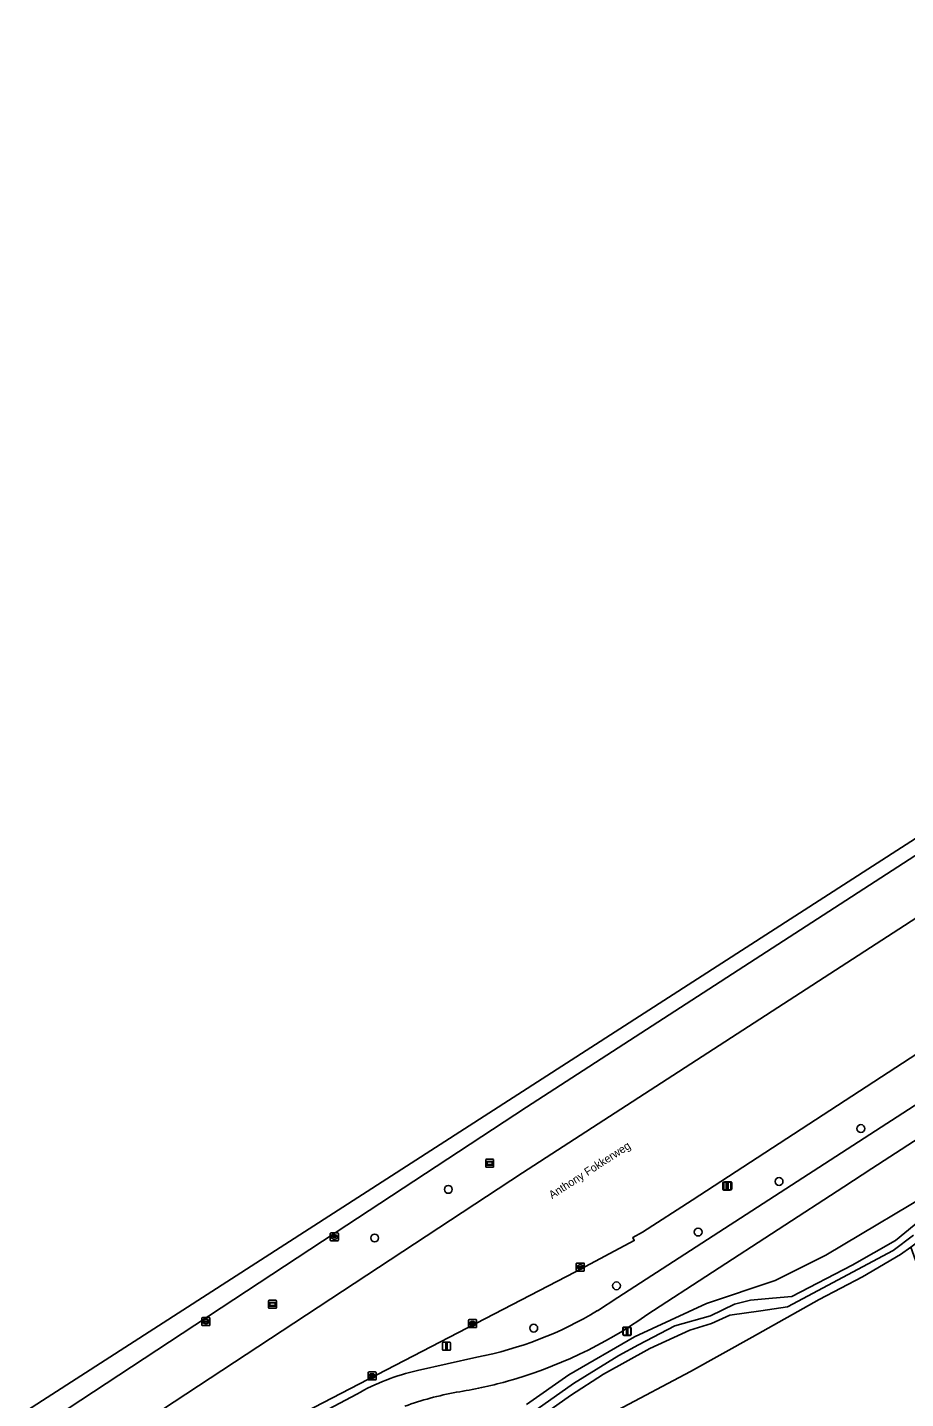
# Model space of a CAD drawing. Extents: x 156061 to 157804, y 383437 to 385640.
# Drawn here: x 156083.9 to 156193.6, y 385371.7 to 385543 of the extents above; entities that cross this region are included whole.
import ezdxf

# ---------------------------------------------------------------- set-up
doc = ezdxf.new("R2010")
doc.units = 0
for name, color, linetype in [('IMGEO_Berm_groen', 7, 'Continuous'), ('IMGEO_Boom', 7, 'Continuous'), ('IMGEO_Fietspad_gesloten', 7, 'Continuous'), ('IMGEO_Groenvoorziening', 7, 'Continuous'), ('IMGEO_Informatiebord', 7, 'Continuous'), ('IMGEO_Kolk', 7, 'Continuous'), ('IMGEO_Lichtmast', 7, 'Continuous'), ('IMGEO_Loofbos', 7, 'Continuous'), ('IMGEO_Oever', 7, 'Continuous'), ('IMGEO_Openbare_ruimte_label', 7, 'Continuous'), ('IMGEO_Rijbaan_regionaal_gesloten', 7, 'Continuous'), ('IMGEO_Waterloop', 7, 'Continuous')]:
    doc.layers.add(name, color=color, linetype=linetype)

msp = doc.modelspace()

# ---------------------------------------------------------------- linework, layer by layer
at = {"layer": 'IMGEO_Berm_groen'}
for points in [[(156360.66, 385543), (156360.46, 385542.87), (156346.09, 385533.56), (156314.1, 385512.84), (156302.47, 385505.41), (156290.49, 385497.87), (156278.52, 385490.5), (156266.95, 385483.55), (156254.78, 385476.36), (156243.16, 385469.51), (156215.23, 385452.76), (156213.93, 385451.91), (156195.47, 385439.96), (156146.25, 385408.11), (156122.36, 385392.42), (156089.02, 385370.47), (156093.27, 385365.39), (156145.76, 385399.91), (156224.68, 385450.98), (156281.69, 385487.99)], [(156362.88, 385518.97), (156357.59, 385515.73), (156355.55, 385514.47), (156333.02, 385500.08), (156304.54, 385485.41), (156304.35, 385485.8), (156253.2, 385452.66), (156166.98, 385396.48), (156160.76, 385392.48), (156159.54, 385391.82), (156159.73, 385391.43), (156152.38, 385387.55), (156100.57, 385360.69), (156097.06, 385358.97), (156097.83, 385357.84), (156097.99, 385357.93), (156125.07, 385372.26)], [(156155.15, 385382.68), (156157.66, 385384.33), (156254.84, 385447.18)], [(156132.64, 385375.2), (156140.06, 385376.88)]]:
    msp.add_lwpolyline(points, dxfattribs=at)
for centre, radius, start, end in [((156131.61, 385421.34), 45.26, 280.765, 301.337), ((156138.57, 385348.64), 27.21, 102.5918, 119.7557)]:
    msp.add_arc(centre, radius, start, end, dxfattribs=at)
at = {"layer": 'IMGEO_Boom'}
for centre in [(156188.04, 385405.43), (156136.5, 385397.83), (156177.82, 385398.82), (156167.71, 385392.5), (156127.3, 385391.76), (156157.51, 385385.79), (156147.17, 385380.5)]:
    msp.add_circle(centre, 0.489, dxfattribs=at)
at = {"layer": 'IMGEO_Fietspad_gesloten'}
for points in [[(156370.19, 385520.48), (156366.79, 385519.18), (156365.93, 385518.78), (156364.24, 385517.92), (156361.44, 385516.31), (156358.41, 385514.31), (156356.83, 385513.33), (156339.62, 385502.15), (156254.84, 385447.18), (156157.66, 385384.33), (156155.15, 385382.68)], [(156161.3, 385382.16), (156185.89, 385398.17), (156189.39, 385400.45), (156267.35, 385450.95)], [(156140.06, 385376.88), (156132.64, 385375.2)], [(156137.5, 385372.48), (156137.53, 385372.49)], [(156125.07, 385372.26), (156097.99, 385357.93), (156097.83, 385357.84), (156095.41, 385356.51), (156096.05, 385355.75), (156098.02, 385353.55), (156101.47, 385355.41), (156101.87, 385355.65), (156108.99, 385359.74), (156113.43, 385362.1)]]:
    msp.add_lwpolyline(points, dxfattribs=at)
for centre, radius, start, end in [((156131.61, 385421.34), 45.26, 280.765, 301.337), ((156128.8, 385428.03), 56.22, 285.4141, 305.3159), ((156138.57, 385348.64), 27.21, 102.5918, 119.7557), ((156144.4, 385334.13), 38.97, 100.1966, 109.9934), ((156128.82, 385427.97), 56.16, 278.9285, 285.4196)]:
    msp.add_arc(centre, radius, start, end, dxfattribs=at)
at = {"layer": 'IMGEO_Groenvoorziening'}
for points in [[(156376.46, 385518.83), (156375.61, 385518.52), (156373.73, 385517.99), (156368.95, 385515.98), (156366.21, 385514.72), (156363.43, 385513.21), (156271.3, 385453.51), (156267.35, 385450.95), (156189.39, 385400.45), (156185.89, 385398.17), (156161.3, 385382.16)], [(156146.27, 385370.97), (156151.56, 385374.68), (156159.75, 385379.43), (156168.75, 385383.56), (156177.32, 385386.43), (156183.65, 385389.61), (156198.62, 385398.53)], [(156137.53, 385372.49), (156137.5, 385372.48)]]:
    msp.add_lwpolyline(points, dxfattribs=at)
for centre, radius, start, end in [((156128.8, 385428.03), 56.22, 285.4141, 305.3159), ((156144.4, 385334.13), 38.97, 100.1966, 109.9934), ((156128.82, 385427.97), 56.16, 278.9285, 285.4196)]:
    msp.add_arc(centre, radius, start, end, dxfattribs=at)
at = {"layer": 'IMGEO_Informatiebord'}
for p, q in [((156141.27, 385401.59), (156142.06, 385401.59)), ((156142.06, 385401.59), (156141.27, 385401.59)), ((156141.17, 385400.69), (156141.17, 385401.49)), ((156141.17, 385401.49), (156141.17, 385400.69)), ((156142.06, 385400.59), (156141.27, 385400.59)), ((156141.27, 385400.59), (156142.06, 385400.59)), ((156142.16, 385401.49), (156142.16, 385400.69)), ((156142.16, 385400.69), (156142.16, 385401.49)), ((156114.04, 385383.08), (156114.04, 385383.88)), ((156114.04, 385383.88), (156114.04, 385383.08)), ((156114.14, 385383.98), (156114.93, 385383.98)), ((156114.93, 385383.98), (156114.14, 385383.98)), ((156114.93, 385382.98), (156114.14, 385382.98)), ((156114.14, 385382.98), (156114.93, 385382.98)), ((156115.03, 385383.88), (156115.03, 385383.08)), ((156115.03, 385383.08), (156115.03, 385383.88))]:
    msp.add_line(p, q, dxfattribs=at)
for points in [[(156141.27, 385401.33), (156142.06, 385401.33), (156142.06, 385400.86), (156141.27, 385400.86), (156141.27, 385401.33)], [(156141.34, 385401.26), (156141.34, 385400.93), (156141.99, 385400.93), (156141.99, 385401.26), (156141.34, 385401.26)], [(156114.15, 385383.72), (156114.93, 385383.72), (156114.93, 385383.25), (156114.15, 385383.25), (156114.15, 385383.72)], [(156114.21, 385383.65), (156114.21, 385383.32), (156114.87, 385383.32), (156114.87, 385383.65), (156114.21, 385383.65)]]:
    msp.add_lwpolyline(points, dxfattribs=at)
for centre, start, end in [((156141.27, 385401.49), 90, 180), ((156141.27, 385401.49), 90, 180), ((156142.06, 385401.49), 0, 90), ((156142.06, 385401.49), 360, 90), ((156141.27, 385400.69), 180, 270), ((156141.27, 385400.69), 180, 270), ((156142.06, 385400.69), 270, 0), ((156142.06, 385400.69), 270, 0), ((156114.14, 385383.88), 90, 180), ((156114.14, 385383.88), 90, 180), ((156114.14, 385383.08), 180, 270), ((156114.14, 385383.08), 180, 270), ((156114.93, 385383.88), 0, 90), ((156114.93, 385383.88), 360, 90), ((156114.93, 385383.08), 270, 0), ((156114.93, 385383.08), 270, 0)]:
    msp.add_arc(centre, 0.1, start, end, dxfattribs=at)
at = {"layer": 'IMGEO_Kolk'}
for p, q in [((156121.76, 385391.47), (156121.76, 385392.32)), ((156121.84, 385392.39), (156122.69, 385392.39)), ((156122.69, 385391.39), (156121.84, 385391.39)), ((156122.02, 385391.89), (156122.02, 385391.9)), ((156122.46, 385391.85), (156122.06, 385391.85)), ((156122.07, 385391.94), (156122.46, 385391.94)), ((156122.25, 385392.17), (156122.28, 385392.17)), ((156122.27, 385391.61), (156122.25, 385391.61)), ((156122.51, 385391.9), (156122.51, 385391.89)), ((156122.77, 385392.32), (156122.77, 385391.47)), ((156152.49, 385387.7), (156152.49, 385388.56)), ((156152.57, 385388.63), (156153.42, 385388.63)), ((156152.75, 385388.12), (156152.75, 385388.14)), ((156153.19, 385388.09), (156152.79, 385388.09)), ((156152.8, 385388.17), (156153.19, 385388.17)), ((156152.98, 385388.41), (156153.01, 385388.41)), ((156153, 385387.85), (156152.98, 385387.85)), ((156153.24, 385388.14), (156153.24, 385388.12)), ((156153.49, 385388.56), (156153.49, 385387.7)), ((156153.42, 385387.63), (156152.57, 385387.63)), ((156105.72, 385380.9), (156105.72, 385381.75)), ((156105.8, 385381.83), (156106.65, 385381.83)), ((156105.98, 385381.32), (156105.98, 385381.33)), ((156106.02, 385381.37), (156106.42, 385381.37)), ((156106.42, 385381.28), (156106.02, 385381.28)), ((156106.21, 385381.61), (156106.23, 385381.61)), ((156106.23, 385381.05), (156106.21, 385381.05)), ((156106.46, 385381.33), (156106.46, 385381.32)), ((156106.72, 385381.75), (156106.72, 385380.9)), ((156139.03, 385380.64), (156139.03, 385381.49)), ((156139.1, 385381.56), (156139.95, 385381.56)), ((156139.28, 385381.06), (156139.28, 385381.07)), ((156139.72, 385381.02), (156139.32, 385381.02)), ((156139.33, 385381.11), (156139.72, 385381.11)), ((156139.51, 385381.34), (156139.54, 385381.34)), ((156139.77, 385381.07), (156139.77, 385381.06)), ((156140.03, 385381.49), (156140.03, 385380.64)), ((156106.65, 385380.83), (156105.8, 385380.83)), ((156139.95, 385380.56), (156139.1, 385380.56)), ((156139.54, 385380.78), (156139.51, 385380.78)), ((156126.48, 385374.11), (156126.48, 385374.96)), ((156126.55, 385375.03), (156127.4, 385375.03)), ((156126.73, 385374.53), (156126.73, 385374.54)), ((156127.17, 385374.49), (156126.77, 385374.49)), ((156126.78, 385374.58), (156127.18, 385374.58)), ((156126.96, 385374.81), (156126.99, 385374.81)), ((156126.99, 385374.25), (156126.96, 385374.25)), ((156127.22, 385374.54), (156127.22, 385374.53)), ((156127.48, 385374.96), (156127.48, 385374.11)), ((156127.4, 385374.03), (156126.55, 385374.03))]:
    msp.add_line(p, q, dxfattribs=at)
for points in [[(156121.76, 385391.47), (156121.76, 385392.32)], [(156121.84, 385392.39), (156122.69, 385392.39)], [(156122.69, 385391.39), (156121.84, 385391.39)], [(156122.77, 385392.32), (156122.77, 385391.47)], [(156152.49, 385387.7), (156152.49, 385388.56)], [(156152.57, 385388.63), (156153.42, 385388.63)], [(156153.49, 385388.56), (156153.49, 385387.7)], [(156153.42, 385387.63), (156152.57, 385387.63)], [(156105.72, 385380.9), (156105.72, 385381.75)], [(156105.8, 385381.83), (156106.65, 385381.83)], [(156106.72, 385381.75), (156106.72, 385380.9)], [(156139.03, 385380.64), (156139.03, 385381.49)], [(156139.1, 385381.56), (156139.95, 385381.56)], [(156140.03, 385381.49), (156140.03, 385380.64)], [(156106.65, 385380.83), (156105.8, 385380.83)], [(156139.95, 385380.56), (156139.1, 385380.56)], [(156126.48, 385374.11), (156126.48, 385374.96)], [(156126.55, 385375.03), (156127.4, 385375.03)], [(156127.48, 385374.96), (156127.48, 385374.11)], [(156127.4, 385374.03), (156126.55, 385374.03)]]:
    msp.add_lwpolyline(points, dxfattribs=at)
for centre, radius, start, end in [((156121.84, 385392.32), 0.0765, 91.552, 178.448), ((156121.84, 385392.32), 0.0765, 91.552, 178.448), ((156121.84, 385391.47), 0.0765, 181.552, 268.448), ((156121.84, 385391.47), 0.0765, 181.552, 268.448), ((156122.06, 385391.9), 0.0403, 85.8775, 175.7526), ((156122.06, 385391.89), 0.0366, 178.938, 274.7102), ((156122.47, 385391.9), 0.0386, 1.7309, 96.639), ((156122.46, 385391.89), 0.043, 264.8664, 352.4533), ((156122.69, 385392.32), 0.0765, 1.552, 88.448), ((156122.69, 385392.32), 0.0765, 1.552, 88.448), ((156122.69, 385391.47), 0.0765, 271.552, 358.448), ((156122.69, 385391.47), 0.0765, 271.552, 358.448), ((156152.57, 385388.56), 0.0765, 91.552, 178.448), ((156152.57, 385388.56), 0.0765, 91.552, 178.448), ((156152.79, 385388.13), 0.0403, 85.8775, 175.7526), ((156152.79, 385388.12), 0.0366, 178.938, 274.7102), ((156153.2, 385388.14), 0.0386, 1.7309, 96.639), ((156153.19, 385388.13), 0.043, 264.8664, 352.4533), ((156153.42, 385388.56), 0.0765, 1.552, 88.448), ((156153.42, 385388.56), 0.0765, 1.552, 88.448), ((156152.57, 385387.71), 0.0765, 181.552, 268.448), ((156152.57, 385387.71), 0.0765, 181.552, 268.448), ((156153.42, 385387.71), 0.0765, 271.552, 358.448), ((156153.42, 385387.71), 0.0765, 271.552, 358.448), ((156105.8, 385381.75), 0.0765, 91.552, 178.448), ((156105.8, 385381.75), 0.0765, 91.552, 178.448), ((156106.02, 385381.33), 0.0403, 85.8775, 175.7526), ((156106.02, 385381.32), 0.0366, 178.938, 274.7102), ((156106.43, 385381.33), 0.0386, 1.7309, 96.639), ((156106.42, 385381.33), 0.043, 264.8664, 352.4533), ((156106.65, 385381.75), 0.0765, 1.552, 88.448), ((156106.65, 385381.75), 0.0765, 1.552, 88.448), ((156139.1, 385381.49), 0.0765, 91.552, 178.448), ((156139.1, 385381.49), 0.0765, 91.552, 178.448), ((156139.32, 385381.07), 0.0403, 85.8775, 175.7526), ((156139.32, 385381.06), 0.0366, 178.938, 274.7102), ((156139.73, 385381.07), 0.0386, 1.7309, 96.639), ((156139.73, 385381.06), 0.043, 264.8664, 352.4533), ((156139.95, 385381.49), 0.0765, 1.552, 88.448), ((156139.95, 385381.49), 0.0765, 1.552, 88.448), ((156105.8, 385380.9), 0.0765, 181.552, 268.448), ((156105.8, 385380.9), 0.0765, 181.552, 268.448), ((156106.65, 385380.9), 0.0765, 271.552, 358.448), ((156106.65, 385380.9), 0.0765, 271.552, 358.448), ((156139.1, 385380.64), 0.0765, 181.552, 268.448), ((156139.1, 385380.64), 0.0765, 181.552, 268.448), ((156139.95, 385380.64), 0.0765, 271.552, 358.448), ((156139.95, 385380.64), 0.0765, 271.552, 358.448), ((156126.55, 385374.96), 0.0765, 91.552, 178.448), ((156126.55, 385374.96), 0.0765, 91.552, 178.448), ((156126.78, 385374.54), 0.0403, 85.8775, 175.7526), ((156126.77, 385374.53), 0.0366, 178.938, 274.7102), ((156127.18, 385374.53), 0.043, 264.8664, 352.4533), ((156127.18, 385374.54), 0.0386, 1.7309, 96.639), ((156127.4, 385374.96), 0.0765, 1.552, 88.448), ((156127.4, 385374.96), 0.0765, 1.552, 88.448), ((156126.55, 385374.11), 0.0765, 181.552, 268.448), ((156126.55, 385374.11), 0.0765, 181.552, 268.448), ((156127.4, 385374.11), 0.0765, 271.552, 358.448), ((156127.4, 385374.11), 0.0765, 271.552, 358.448)]:
    msp.add_arc(centre, radius, start, end, dxfattribs=at)
for centre, major_axis, ratio, start_param, end_param in [((156122.25, 385391.89), (-0.387, 0.002), 0.722429, 4.712389, 7.853982), ((156122.28, 385391.89), (-0.39, 0.002), 0.717154, 1.570796, 4.712389), ((156152.98, 385388.13), (-0.387, 0.002), 0.722429, 4.712389, 7.853982), ((156153, 385388.13), (-0.39, 0.002), 0.717154, 1.570796, 4.712389), ((156106.21, 385381.33), (-0.387, 0.002), 0.722429, 4.712389, 7.853982), ((156106.23, 385381.33), (-0.39, 0.002), 0.717154, 1.570796, 4.712389), ((156139.51, 385381.06), (-0.387, 0.002), 0.722429, 4.712389, 7.853982), ((156139.54, 385381.06), (-0.39, 0.002), 0.717154, 1.570796, 4.712389), ((156126.96, 385374.53), (-0.387, 0.002), 0.722429, 4.712389, 7.853982), ((156126.99, 385374.53), (-0.39, 0.002), 0.717154, 1.570796, 4.712389)]:
    msp.add_ellipse(centre, major_axis=major_axis, ratio=ratio, start_param=start_param, end_param=end_param, dxfattribs=at)
at = {"layer": 'IMGEO_Lichtmast'}
for p, q in [((156170.81, 385397.85), (156170.81, 385398.65)), ((156170.81, 385398.65), (156170.81, 385397.85)), ((156170.91, 385398.75), (156171.7, 385398.75)), ((156171.7, 385398.75), (156170.91, 385398.75)), ((156170.91, 385397.88), (156170.91, 385398.68)), ((156170.91, 385398.68), (156170.91, 385397.88)), ((156171.01, 385398.78), (156171.8, 385398.78)), ((156171.8, 385398.78), (156171.01, 385398.78)), ((156171.8, 385398.65), (156171.8, 385397.85)), ((156171.8, 385397.85), (156171.8, 385398.65)), ((156171.9, 385398.68), (156171.9, 385397.88)), ((156171.9, 385397.88), (156171.9, 385398.68)), ((156171.7, 385397.75), (156170.91, 385397.75)), ((156170.91, 385397.75), (156171.7, 385397.75)), ((156171.8, 385397.78), (156171.01, 385397.78)), ((156171.01, 385397.78), (156171.8, 385397.78)), ((156158.32, 385379.74), (156158.32, 385380.54)), ((156158.32, 385380.54), (156158.32, 385379.74)), ((156158.35, 385379.68), (156158.35, 385380.48)), ((156158.35, 385380.48), (156158.35, 385379.68)), ((156158.42, 385380.64), (156159.21, 385380.64)), ((156159.21, 385380.64), (156158.42, 385380.64)), ((156159.21, 385379.64), (156158.42, 385379.64)), ((156158.42, 385379.64), (156159.21, 385379.64)), ((156158.45, 385380.58), (156159.24, 385380.58)), ((156159.24, 385380.58), (156158.45, 385380.58)), ((156159.24, 385379.58), (156158.45, 385379.58)), ((156158.45, 385379.58), (156159.24, 385379.58)), ((156159.31, 385380.54), (156159.31, 385379.74)), ((156159.31, 385379.74), (156159.31, 385380.54)), ((156159.34, 385380.48), (156159.34, 385379.68)), ((156159.34, 385379.68), (156159.34, 385380.48)), ((156135.77, 385377.83), (156135.77, 385378.63)), ((156135.77, 385378.63), (156135.77, 385377.83)), ((156135.87, 385378.73), (156136.66, 385378.73)), ((156136.66, 385378.73), (156135.87, 385378.73)), ((156136.66, 385377.73), (156135.87, 385377.73)), ((156135.87, 385377.73), (156136.66, 385377.73)), ((156136.76, 385378.63), (156136.76, 385377.83)), ((156136.76, 385377.83), (156136.76, 385378.63))]:
    msp.add_line(p, q, dxfattribs=at)
for points in [[(156171.23, 385398.63), (156171.38, 385398.63), (156171.38, 385397.88), (156171.23, 385397.88), (156171.23, 385398.63)], [(156171.33, 385398.66), (156171.48, 385398.66), (156171.48, 385397.91), (156171.33, 385397.91), (156171.33, 385398.66)], [(156158.74, 385380.52), (156158.89, 385380.52), (156158.89, 385379.77), (156158.74, 385379.77), (156158.74, 385380.52)], [(156158.77, 385380.46), (156158.92, 385380.46), (156158.92, 385379.71), (156158.77, 385379.71), (156158.77, 385380.46)], [(156136.19, 385378.61), (156136.34, 385378.61), (156136.34, 385377.86), (156136.19, 385377.86), (156136.19, 385378.61)]]:
    msp.add_lwpolyline(points, dxfattribs=at)
for centre, start, end in [((156170.91, 385398.65), 90, 180), ((156170.91, 385398.65), 90, 180), ((156171.01, 385398.68), 90, 180), ((156171.01, 385398.68), 90, 180), ((156171.7, 385398.65), 0, 90), ((156171.7, 385398.65), 360, 90), ((156171.8, 385398.68), 0, 90), ((156171.8, 385398.68), 360, 90), ((156170.91, 385397.85), 180, 270), ((156170.91, 385397.85), 180, 270), ((156171.01, 385397.88), 180, 270), ((156171.01, 385397.88), 180, 270), ((156171.7, 385397.85), 270, 0), ((156171.7, 385397.85), 270, 0), ((156171.8, 385397.88), 270, 0), ((156171.8, 385397.88), 270, 0), ((156158.42, 385380.54), 90, 180), ((156158.42, 385380.54), 90, 180), ((156158.42, 385379.74), 180, 270), ((156158.42, 385379.74), 180, 270), ((156158.45, 385380.48), 90, 180), ((156158.45, 385380.48), 90, 180), ((156158.45, 385379.68), 180, 270), ((156158.45, 385379.68), 180, 270), ((156159.21, 385380.54), 0, 90), ((156159.21, 385380.54), 360, 90), ((156159.21, 385379.74), 270, 0), ((156159.21, 385379.74), 270, 0), ((156159.24, 385380.48), 0, 90), ((156159.24, 385380.48), 360, 90), ((156159.24, 385379.68), 270, 0), ((156159.24, 385379.68), 270, 0), ((156135.87, 385378.63), 90, 180), ((156135.87, 385378.63), 90, 180), ((156135.87, 385377.83), 180, 270), ((156135.87, 385377.83), 180, 270), ((156136.66, 385378.63), 0, 90), ((156136.66, 385378.63), 360, 90), ((156136.66, 385377.83), 270, 0), ((156136.66, 385377.83), 270, 0)]:
    msp.add_arc(centre, 0.1, start, end, dxfattribs=at)
at = {"layer": 'IMGEO_Loofbos'}
msp.add_lwpolyline([(156209.43, 385312.37), (156207.27, 385318.03), (156200.47, 385373.29), (156194.26, 385390.62), (156192.99, 385389.69), (156188.26, 385386.89), (156182.84, 385384.09), (156174.44, 385379.36), (156166.74, 385375.08), (156157.64, 385370.27), (156148.02, 385365.37), (156139.09, 385361.08), (156138.69, 385359.88)], dxfattribs=at)
at = {"layer": 'IMGEO_Oever'}
for points in [[(156192.99, 385389.69), (156194.26, 385390.62), (156198.19, 385393.51), (156201.34, 385395.08), (156231.18, 385413.28), (156283.45, 385445.59), (156297.27, 385454.14), (156298.76, 385455.01), (156299.55, 385455.99), (156300.52, 385457.57), (156300.12, 385458.01), (156299.67, 385458.5), (156297.74, 385457.95), (156292.41, 385454.18), (156278.01, 385445.95), (156256.32, 385433.03), (156229.22, 385416.91), (156198.62, 385398.53), (156183.65, 385389.61), (156177.32, 385386.43), (156168.75, 385383.56), (156159.75, 385379.43), (156151.56, 385374.68), (156146.27, 385370.97)], [(156146.18, 385369.39), (156152.13, 385373.59), (156157.82, 385377.09), (156160.27, 385378.4), (156164.81, 385380.77), (156169.24, 385382.05), (156172.25, 385383.48), (156174.26, 385384), (156176.98, 385384.26), (156179.43, 385384.44), (156186.95, 385388.38), (156192.37, 385391.44), (156195.87, 385394.33)], [(156194.61, 385392.1), (156192.07, 385390.18), (156178.86, 385383.18), (156175.53, 385382.66), (156171.68, 385382.13), (156169.39, 385381.06), (156166.65, 385380.24), (156161.67, 385377.97), (156155.89, 385374.73), (156151.78, 385372.1), (156147.23, 385368.87)], [(156134.91, 385352.73), (156136.1, 385353.88), (156137.15, 385354.81), (156139.11, 385356.54), (156138.69, 385359.88), (156139.09, 385361.08), (156148.02, 385365.37), (156157.64, 385370.27), (156166.74, 385375.08), (156174.44, 385379.36), (156182.84, 385384.09), (156188.26, 385386.89), (156192.99, 385389.69)]]:
    msp.add_lwpolyline(points, dxfattribs=at)
at = {"layer": 'IMGEO_Rijbaan_regionaal_gesloten'}
msp.add_lwpolyline([(156083.92, 385370.25), (156085.61, 385368.22), (156089.02, 385370.47), (156122.36, 385392.42), (156146.25, 385408.11), (156195.47, 385439.96), (156213.93, 385451.91), (156215.23, 385452.76), (156243.16, 385469.51), (156254.78, 385476.36), (156266.95, 385483.55), (156278.52, 385490.5), (156290.49, 385497.87), (156302.47, 385505.41), (156314.1, 385512.84), (156346.09, 385533.56), (156343.56, 385537.43), (156083.92, 385370.25)], dxfattribs=at)
msp.add_lwpolyline([(156355.55, 385514.47), (156357.59, 385515.73), (156347.87, 385530.83), (156281.69, 385487.99), (156224.68, 385450.98), (156145.76, 385399.91), (156093.27, 385365.39), (156089.86, 385363.15), (156095.26, 385356.69), (156095.41, 385356.51), (156097.83, 385357.84), (156097.06, 385358.97), (156100.57, 385360.69), (156152.38, 385387.55), (156159.73, 385391.43), (156159.54, 385391.82), (156160.76, 385392.48), (156166.98, 385396.48), (156253.2, 385452.66), (156304.35, 385485.8), (156304.54, 385485.41), (156333.02, 385500.08)], close=True, dxfattribs=at)
at = {"layer": 'IMGEO_Waterloop'}
for points in [[(156195.87, 385394.33), (156192.37, 385391.44), (156186.95, 385388.38), (156179.43, 385384.44), (156176.98, 385384.26), (156174.26, 385384), (156172.25, 385383.48), (156169.24, 385382.05), (156164.81, 385380.77), (156160.27, 385378.4), (156157.82, 385377.09), (156152.13, 385373.59), (156146.18, 385369.39)], [(156147.23, 385368.87), (156151.78, 385372.1), (156155.89, 385374.73), (156161.67, 385377.97), (156166.65, 385380.24), (156169.39, 385381.06), (156171.68, 385382.13), (156175.53, 385382.66), (156178.86, 385383.18), (156192.07, 385390.18), (156194.61, 385392.1)]]:
    msp.add_lwpolyline(points, dxfattribs=at)

# ---------------------------------------------------------------- texts
at = {"layer": 'IMGEO_Openbare_ruimte_label'}
msp.add_text('Anthony Fokkerweg', height=1, rotation=32.959, dxfattribs=at).set_placement((156149.46, 385396.61))

doc.saveas('drawing.dxf')
